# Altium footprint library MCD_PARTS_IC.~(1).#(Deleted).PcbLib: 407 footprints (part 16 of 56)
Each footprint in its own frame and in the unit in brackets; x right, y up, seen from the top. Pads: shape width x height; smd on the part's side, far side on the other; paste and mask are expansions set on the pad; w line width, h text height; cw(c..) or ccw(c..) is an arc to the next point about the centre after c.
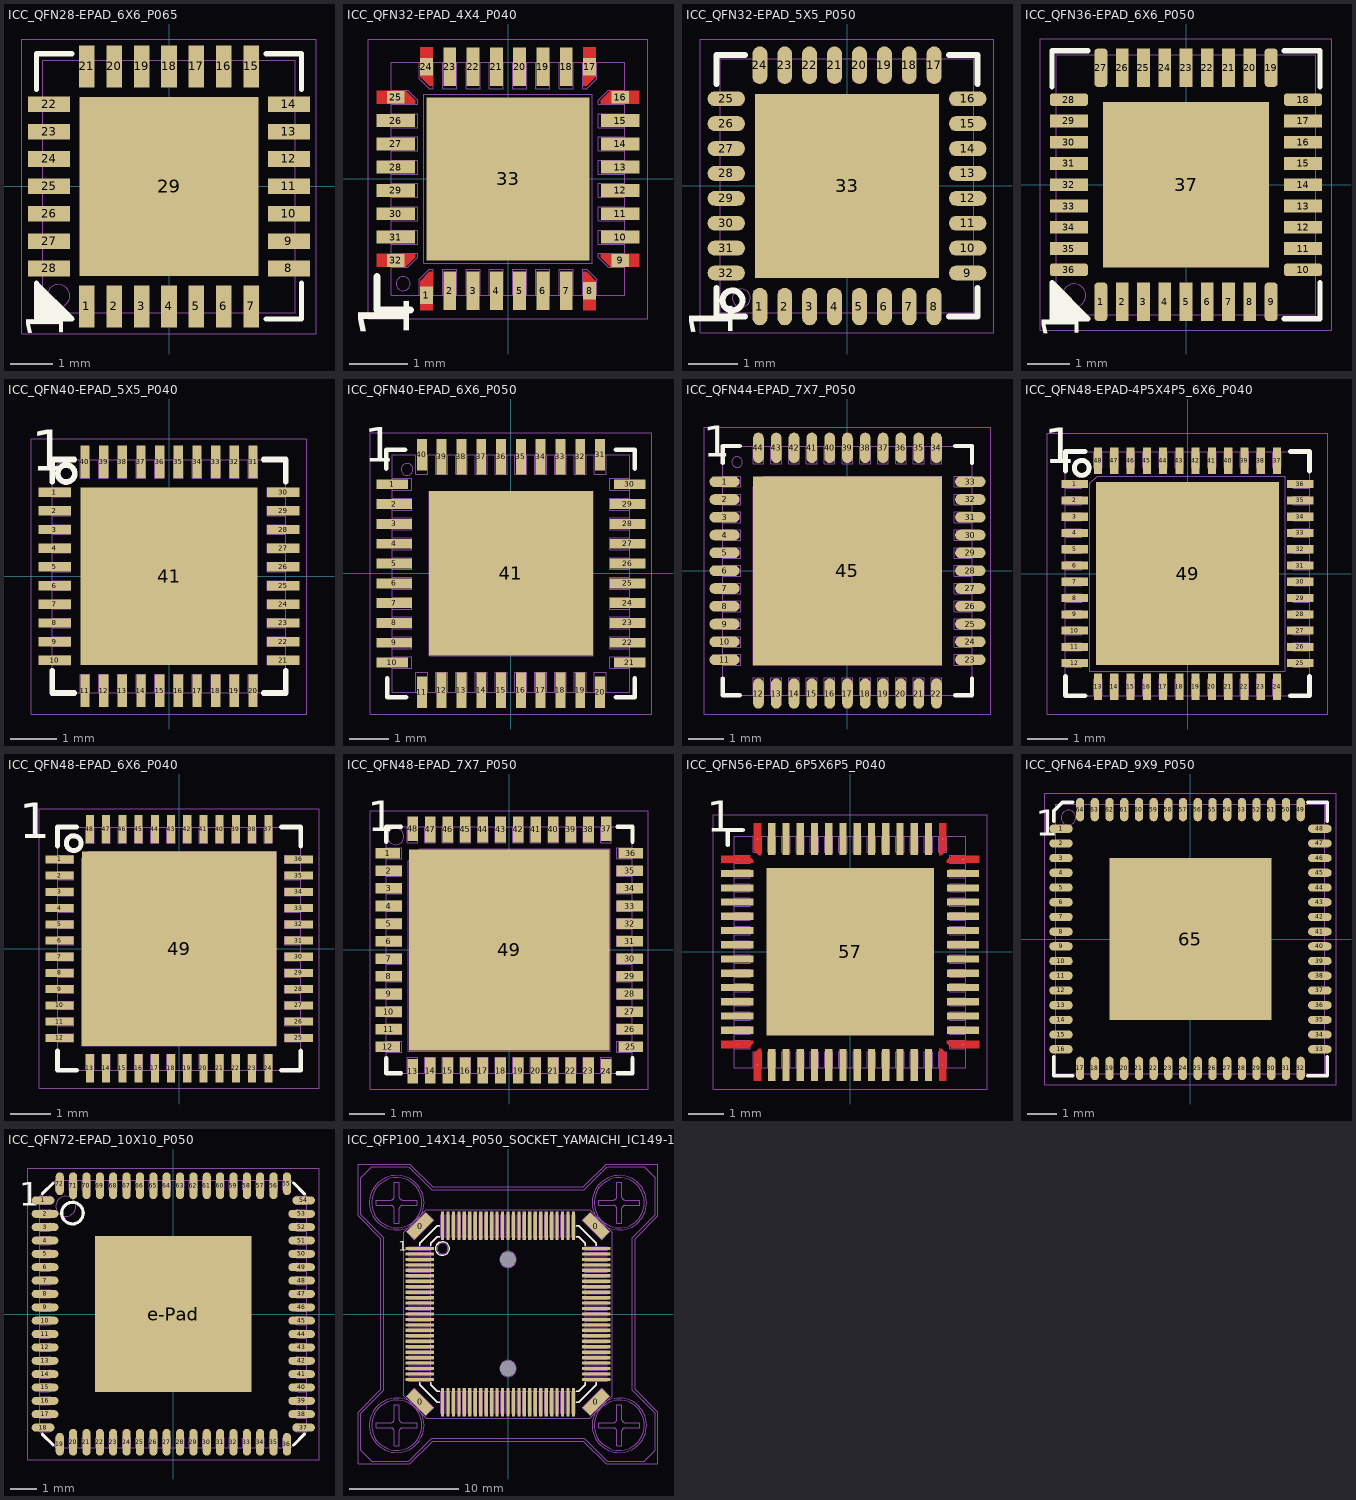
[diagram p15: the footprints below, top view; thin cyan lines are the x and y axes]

## ICC_QFN28-EPAD_6X6_P065 [mm] "MCD-02210"
height 1
pads (29):
  rect 0.37x1 smd mask+0.05: 1(-1.95,-2.85) 2(-1.3,-2.85) 3(-0.65,-2.85) 4(0,-2.85) 5(0.65,-2.85) 6(1.3,-2.85) 7(1.95,-2.85) 15(1.95,2.85) 16(1.3,2.85) 17(0.65,2.85) 18(0,2.85) 19(-0.65,2.85) 20(-1.3,2.85) 21(-1.95,2.85)
  rect 1x0.37 smd mask+0.05: 8(2.85,-1.95) 9(2.85,-1.3) 10(2.85,-0.65) 11(2.85,0) 12(2.85,0.65) 13(2.85,1.3) 14(2.85,1.95) 22(-2.85,1.95) 23(-2.85,1.3) 24(-2.85,0.65) 25(-2.85,0) 26(-2.85,-0.65) 27(-2.85,-1.3) 28(-2.85,-1.95)
  rect 4.25x4.25 smd mask+0.05: 29(0,0)
Top Overlay:
  lines w0.12: -3.15,-2.9 -2.9,-3.15 ; -3.15,-2.75 -2.75,-3.15 ; -3.15,-2.6 -2.6,-3.15 ; -3.15,-2.45 -2.45,-3.15 ; -3.15,2.3 -3.15,3.15 -2.3,3.15 ; -2.75,-2.75 -3.15,-3.15 ; 2.3,-3.15 3.15,-3.15 3.15,-2.3 ; 2.3,3.15 3.15,3.15 3.15,2.3 ; -3.15,-3.15 -2.3,-3.15 -3.15,-2.3 -3.15,-3.15
  text "1" at -2.225,-3.625 h1.5
M14-Top Assembly:
  circle w0.01: c-2.625,-2.6 r0.27
  lines w0.01: -3,-3 3,-3 3,3 -3,3 -3,-3
  text "'.Designator'" at -2,-0.5 h0.75
M16-Top Courtyard:
  lines w0.01: -3.5,-3.5 3.5,-3.5 3.5,3.5 -3.5,3.5 -3.5,-3.5
3D body "User Library-QFN 28-Pin 0_65mm Pitch.STEP": height 1, standoff 0, extent -3.01,-3.01 3.01,3.01
3D body: height 1, standoff 0, extent -3.055,-3.055 3.055,3.055

## ICC_QFN32-EPAD_4X4_P040 [mm]
height 0.9
pads (33):
  rect 0.22x0.3 smd mask+0.05: 1(-1.4,-2) 8(1.4,-1.925) 17(1.4,1.925) 24(-1.4,1.925)
  rect 0.22x0.66 smd mask+0.05: 2(-1,-1.925) 3(-0.6,-1.925) 4(-0.2,-1.925) 5(0.2,-1.925) 6(0.6,-1.925) 7(1,-1.925) 18(1,1.925) 19(0.6,1.925) 20(0.2,1.925) 21(-0.2,1.925) 22(-0.6,1.925) 23(-1,1.925)
  rect 0.3x0.22 smd mask+0.05: 9(1.925,-1.4) 16(1.925,1.4) 25(-1.925,1.4) 32(-1.925,-1.4)
  rect 0.66x0.22 smd mask+0.05: 10(1.925,-1) 11(1.925,-0.6) 12(1.925,-0.2) 13(1.925,0.2) 14(1.925,0.6) 15(1.925,1) 26(-1.925,1) 27(-1.925,0.6) 28(-1.925,0.2) 29(-1.925,-0.2) 30(-1.925,-0.6) 31(-1.925,-1)
  rect 2.8x2.8 smd mask+0.05: 33(0,0)
Top Layer:
  region: 1.29,-2.255 1.29,-1.595 1.35,-1.595 1.51,-1.755 1.51,-2.255
  region: -1.29,-2.255 -1.29,-1.595 -1.35,-1.595 -1.51,-1.755 -1.51,-2.255
  region: -2.255,-1.29 -1.595,-1.29 -1.595,-1.35 -1.755,-1.51 -2.255,-1.51
  region: -2.255,1.29 -1.595,1.29 -1.595,1.35 -1.755,1.51 -2.255,1.51
  region: 2.255,1.29 1.595,1.29 1.595,1.35 1.755,1.51 2.255,1.51
  region: 2.255,-1.29 1.595,-1.29 1.595,-1.35 1.755,-1.51 2.255,-1.51
  region: 1.29,2.255 1.29,1.595 1.35,1.595 1.51,1.755 1.51,2.255
  region: -1.29,2.255 -1.29,1.595 -1.35,1.595 -1.51,1.755 -1.51,2.255
Top Overlay:
  lines w0.12: -2.25,-1.675 -2.25,-2.25 -1.675,-2.25
  text "1" at -1.4,-2.75 h1.5
M14-Top Assembly:
  circle w0.01: c-1.8,-1.8 r0.12
  lines w0.01: -2,-1.52 -1.72,-1.52 -1.55,-1.35 -1.55,-1.28 -2,-1.28 ; -2,-1.12 -1.55,-1.12 -1.55,-0.88 -2,-0.88 ; -2,-0.72 -1.55,-0.72 -1.55,-0.48 -2,-0.48 ; -2,-0.32 -1.55,-0.32 -1.55,-0.08 -2,-0.08 ; -2,0.08 -1.55,0.08 -1.55,0.32 -2,0.32 ; -2,0.48 -1.55,0.48 -1.55,0.72 -2,0.72 ; -2,0.88 -1.55,0.88 -1.55,1.12 -2,1.12 ; -2,1.28 -1.55,1.28 -1.55,1.35 -1.72,1.52 -2,1.52 ; -1.52,-2 -1.52,-1.72 -1.35,-1.55 -1.28,-1.55 -1.28,-2 ; -1.52,2 -1.52,1.72 -1.35,1.55 -1.28,1.55 -1.28,2 ; -1.12,-2 -1.12,-1.55 -0.88,-1.55 -0.88,-2 ; -1.12,2 -1.12,1.55 -0.88,1.55 -0.88,2 ; -0.72,-2 -0.72,-1.55 -0.48,-1.55 -0.48,-2 ; -0.72,2 -0.72,1.55 -0.48,1.55 -0.48,2 ; -0.32,-2 -0.32,-1.55 -0.08,-1.55 -0.08,-2 ; -0.32,2 -0.32,1.55 -0.08,1.55 -0.08,2 ; 0.08,-2 0.08,-1.55 0.32,-1.55 0.32,-2 ; 0.08,2 0.08,1.55 0.32,1.55 0.32,2 ; 0.48,-2 0.48,-1.55 0.72,-1.55 0.72,-2 ; 0.48,2 0.48,1.55 0.72,1.55 0.72,2 ; 0.88,-2 0.88,-1.55 1.12,-1.55 1.12,-2 ; 0.88,2 0.88,1.55 1.12,1.55 1.12,2 ; 1.28,-2 1.28,-1.55 1.35,-1.55 1.52,-1.72 1.52,-2 ; 1.28,2 1.28,1.55 1.35,1.55 1.52,1.72 1.52,2 ; 2,-1.52 1.72,-1.52 1.55,-1.35 1.55,-1.28 2,-1.28 ; 2,-1.12 1.55,-1.12 1.55,-0.88 2,-0.88 ; 2,-0.72 1.55,-0.72 1.55,-0.48 2,-0.48 ; 2,-0.32 1.55,-0.32 1.55,-0.08 2,-0.08 ; 2,0.08 1.55,0.08 1.55,0.32 2,0.32 ; 2,0.48 1.55,0.48 1.55,0.72 2,0.72 ; 2,0.88 1.55,0.88 1.55,1.12 2,1.12 ; 2,1.28 1.55,1.28 1.55,1.35 1.72,1.52 2,1.52 ; -2,-2 -2,2 2,2 2,-2 -2,-2 ; -1.45,-1.45 -1.45,1.45 1.45,1.45 1.45,-1.45 -1.45,-1.45
  text "33" at -0.275,-0.15 h0.5
  text "8" at 1.3,-1.95 h0.5
  text "1" at -1.475,-1.95 h0.5
  text "'.Designator'" at 0,0 h0.75
  text "16" at 1.95,1.2 h0.5
  text "9" at 1.95,-1.475 h0.5
  text "24" at -1.15,1.95 h0.5
  text "17" at 1.625,1.95 h0.5
  text "32" at -1.95,-1.125 h0.5
  text "25" at -1.95,1.625 h0.5
M16-Top Courtyard:
  lines w0.01: -2.4,-2.4 2.4,-2.4 2.4,2.4 -2.4,2.4 -2.4,-2.4
3D body: height 0.9, standoff 0, extent -2.005,-2.005 2.005,2.005
3D body: height 0.91, standoff 0.9, extent -1.92,-1.92 -1.68,-1.68

## ICC_QFN32-EPAD_5X5_P050 [mm]
height 1
pads (33):
  oval 0.3x0.75 smd mask+0.05: 1(-1.75,-2.425) 2(-1.25,-2.425) 3(-0.75,-2.425) 4(-0.25,-2.425) 5(0.25,-2.425) 6(0.75,-2.425) 7(1.25,-2.425) 8(1.75,-2.425) 17(1.75,2.425) 18(1.25,2.425) 19(0.75,2.425) 20(0.25,2.425) 21(-0.25,2.425) 22(-0.75,2.425) 23(-1.25,2.425) 24(-1.75,2.425)
  oval 0.75x0.3 smd mask+0.05: 9(2.425,-1.75) 10(2.425,-1.25) 11(2.425,-0.75) 12(2.425,-0.25) 13(2.425,0.25) 14(2.425,0.75) 15(2.425,1.25) 16(2.425,1.75) 25(-2.425,1.75) 26(-2.425,1.25) 27(-2.425,0.75) 28(-2.425,0.25) 29(-2.425,-0.25) 30(-2.425,-0.75) 31(-2.425,-1.25) 32(-2.425,-1.75)
  rect 3.7x3.7 smd mask+0.05: 33(0,0)
Top Overlay:
  circle w0.12: c-2.3,-2.3 r0.2
  lines w0.12: -2.625,-2.05 -2.625,-2.625 -2.05,-2.625 ; -2.625,2.05 -2.625,2.625 -2.05,2.625 ; 2.05,-2.625 2.625,-2.625 2.625,-2.05 ; 2.05,2.625 2.625,2.625 2.625,2.05
  text "1" at -2,-3.075 h1.5
M14-Top Assembly:
  circle w0.01: c-2.125,-2.25 r0.18
  lines w0.01: -2.55,-1.87 -2.1,-1.87 -2.1,-1.63 -2.55,-1.63 ; -2.55,-1.37 -2.1,-1.37 -2.1,-1.13 -2.55,-1.13 ; -2.55,-0.87 -2.1,-0.87 -2.1,-0.63 -2.55,-0.63 ; -2.55,-0.37 -2.1,-0.37 -2.1,-0.13 -2.55,-0.13 ; -2.55,0.13 -2.1,0.13 -2.1,0.37 -2.55,0.37 ; -2.55,0.63 -2.1,0.63 -2.1,0.87 -2.55,0.87 ; -2.55,1.13 -2.1,1.13 -2.1,1.37 -2.55,1.37 ; -2.55,1.63 -2.1,1.63 -2.1,1.87 -2.55,1.87 ; -1.87,-2.55 -1.87,-2.1 -1.63,-2.1 -1.63,-2.55 ; -1.87,2.55 -1.87,2.1 -1.63,2.1 -1.63,2.55 ; -1.37,-2.55 -1.37,-2.1 -1.13,-2.1 -1.13,-2.55 ; -1.37,2.55 -1.37,2.1 -1.13,2.1 -1.13,2.55 ; -0.87,-2.55 -0.87,-2.1 -0.63,-2.1 -0.63,-2.55 ; -0.87,2.55 -0.87,2.1 -0.63,2.1 -0.63,2.55 ; -0.37,-2.55 -0.37,-2.1 -0.13,-2.1 -0.13,-2.55 ; -0.37,2.55 -0.37,2.1 -0.13,2.1 -0.13,2.55 ; 0.13,-2.55 0.13,-2.1 0.37,-2.1 0.37,-2.55 ; 0.13,2.55 0.13,2.1 0.37,2.1 0.37,2.55 ; 0.63,-2.55 0.63,-2.1 0.87,-2.1 0.87,-2.55 ; 0.63,2.55 0.63,2.1 0.87,2.1 0.87,2.55 ; 1.13,-2.55 1.13,-2.1 1.37,-2.1 1.37,-2.55 ; 1.13,2.55 1.13,2.1 1.37,2.1 1.37,2.55 ; 1.63,-2.55 1.63,-2.1 1.87,-2.1 1.87,-2.55 ; 1.63,2.55 1.63,2.1 1.87,2.1 1.87,2.55 ; 2.55,-1.87 2.1,-1.87 2.1,-1.63 2.55,-1.63 ; 2.55,-1.37 2.1,-1.37 2.1,-1.13 2.55,-1.13 ; 2.55,-0.87 2.1,-0.87 2.1,-0.63 2.55,-0.63 ; 2.55,-0.37 2.1,-0.37 2.1,-0.13 2.55,-0.13 ; 2.55,0.13 2.1,0.13 2.1,0.37 2.55,0.37 ; 2.55,0.63 2.1,0.63 2.1,0.87 2.55,0.87 ; 2.55,1.13 2.1,1.13 2.1,1.37 2.55,1.37 ; 2.55,1.63 2.1,1.63 2.1,1.87 2.55,1.87 ; -2.55,-2.55 -2.55,2.55 2.55,2.55 2.55,-2.55 -2.55,-2.55 ; -1.8,-1.787 -1.8,1.82 1.807,1.82 1.807,-1.787 -1.8,-1.787
  text "33" at -0.275,-0.15 h0.5
  text "32" at -2.45,-1.525 h0.5
  text "25" at -2.45,2 h0.5
  text "24" at -1.975,2.175 h0.5
  text "17" at 1.55,2.15 h0.5
  text "16" at 2.45,1.575 h0.5
  text "9" at 2.45,-1.85 h0.5
  text "8" at 1.65,-2.475 h0.5
  text "1" at -1.8,-2.475 h0.5
  text "'.Designator'" at -2,0.25 h0.75
M16-Top Courtyard:
  lines w0.01: -2.95,-2.95 2.95,-2.95 2.95,2.95 -2.95,2.95 -2.95,-2.95
3D body: height 1, standoff 0, extent -2.55,-2.55 2.55,2.55
3D body "QFN32-EPAD_5X5_P050.STEP": height 0.9, standoff -0.03, extent -2.5,-2.5 2.5,2.5

## ICC_QFN36-EPAD_6X6_P050 [mm]
height 1
pads (37):
  rrect50% 0.3x0.9 smd mask+0.05: 1(-2,-2.75) 9(2,-2.75) 19(2,2.75) 27(-2,2.75)
  rect 0.3x0.9 smd mask+0.05: 2(-1.5,-2.75) 3(-1,-2.75) 4(-0.5,-2.75) 5(0,-2.75) 6(0.5,-2.75) 7(1,-2.75) 8(1.5,-2.75) 20(1.5,2.75) 21(1,2.75) 22(0.5,2.75) 23(0,2.75) 24(-0.5,2.75) 25(-1,2.75) 26(-1.5,2.75)
  rrect50% 0.9x0.3 smd mask+0.05: 10(2.75,-2) 18(2.75,2) 28(-2.75,2) 36(-2.75,-2)
  rect 0.9x0.3 smd mask+0.05: 11(2.75,-1.5) 12(2.75,-1) 13(2.75,-0.5) 14(2.75,0) 15(2.75,0.5) 16(2.75,1) 17(2.75,1.5) 29(-2.75,1.5) 30(-2.75,1) 31(-2.75,0.5) 32(-2.75,0) 33(-2.75,-0.5) 34(-2.75,-1) 35(-2.75,-1.5)
  rect 3.9x3.9 smd mask+0.05: 37(0,0)
Top Overlay:
  lines w0.12: -3.15,-2.9 -2.9,-3.15 ; -3.15,-2.75 -2.75,-3.15 ; -3.15,-2.6 -2.6,-3.15 ; -3.15,-2.45 -2.45,-3.15 ; -3.15,2.3 -3.15,3.15 -2.3,3.15 ; -2.75,-2.75 -3.15,-3.15 ; 2.3,-3.15 3.15,-3.15 3.15,-2.3 ; 2.3,3.15 3.15,3.15 3.15,2.3 ; -3.15,-3.15 -3.15,-2.3 -2.3,-3.15 -3.15,-3.15
  text "1" at -2.225,-3.625 h1.5
M14-Top Assembly:
  circle w0.01: c-2.625,-2.6 r0.27
  lines w0.01: -3.05,-3.05 3.05,-3.05 3.05,3.05 -3.05,3.05 -3.05,-3.05
  text "'.Designator'" at -2,-0.5 h0.75
M16-Top Courtyard:
  lines w0.01: -3.425,-3.425 -3.425,3.425 3.425,3.425 3.425,-3.425 -3.425,-3.425
3D body: height 1, standoff 0, extent -3.055,-3.055 3.055,3.055
3D body "QFN36-EPAD_6X6_P050.STEP": height 0.8, standoff 0, extent -3.06,-3.06 3.06,3.06

## ICC_QFN40-EPAD_5X5_P040 [mm]
height 0.9
pads (41):
  rect 0.7x0.2 smd mask+0.05: 1(-2.45,1.8) 2(-2.45,1.4) 3(-2.45,1) 4(-2.45,0.6) 5(-2.45,0.2) 6(-2.45,-0.2) 7(-2.45,-0.6) 8(-2.45,-1) 9(-2.45,-1.4) 10(-2.45,-1.8) 21(2.45,-1.8) 22(2.45,-1.4) 23(2.45,-1) 24(2.45,-0.6) 25(2.45,-0.2) 26(2.45,0.2) 27(2.45,0.6) 28(2.45,1) 29(2.45,1.4) 30(2.45,1.8)
  rect 0.2x0.7 smd mask+0.05: 11(-1.8,-2.45) 12(-1.4,-2.45) 13(-1,-2.45) 14(-0.6,-2.45) 15(-0.2,-2.45) 16(0.2,-2.45) 17(0.6,-2.45) 18(1,-2.45) 19(1.4,-2.45) 20(1.8,-2.45) 31(1.8,2.45) 32(1.4,2.45) 33(1,2.45) 34(0.6,2.45) 35(0.2,2.45) 36(-0.2,2.45) 37(-0.6,2.45) 38(-1,2.45) 39(-1.4,2.45) 40(-1.8,2.45)
  rect 3.8x3.8 smd mask+0.05: 41(0,0)
Top Overlay:
  circle w0.12: c-2.2,2.2 r0.182
  lines w0.12: -2.5,-2.025 -2.5,-2.5 -2.025,-2.5 ; -2.5,2.025 -2.5,2.5 -2.025,2.5 ; 2.025,-2.5 2.5,-2.5 2.5,-2.025 ; 2.025,2.5 2.5,2.5 2.5,2.025
  text "1" at -2.95,1.975 h1.5
M14-Top Assembly:
  circle w0.01: c-2.225,2.225 r0.23
  lines w0.01: -2.5,-1.9 -2.1,-1.9 -2.1,-1.7 -2.5,-1.7 ; -2.5,-1.5 -2.1,-1.5 -2.1,-1.3 -2.5,-1.3 ; -2.5,-1.1 -2.1,-1.1 -2.1,-0.9 -2.5,-0.9 ; -2.5,-0.7 -2.1,-0.7 -2.1,-0.5 -2.5,-0.5 ; -2.5,-0.3 -2.1,-0.3 -2.1,-0.1 -2.5,-0.1 ; -2.5,0.1 -2.1,0.1 -2.1,0.3 -2.5,0.3 ; -2.5,0.5 -2.1,0.5 -2.1,0.7 -2.5,0.7 ; -2.5,0.9 -2.1,0.9 -2.1,1.1 -2.5,1.1 ; -2.5,1.3 -2.1,1.3 -2.1,1.5 -2.5,1.5 ; -2.5,1.7 -2.1,1.7 -2.1,1.9 -2.5,1.9 ; -1.9,-2.5 -1.9,-2.1 -1.7,-2.1 -1.7,-2.5 ; -1.9,2.5 -1.9,2.1 -1.7,2.1 -1.7,2.5 ; -1.5,-2.5 -1.5,-2.1 -1.3,-2.1 -1.3,-2.5 ; -1.5,2.5 -1.5,2.1 -1.3,2.1 -1.3,2.5 ; -1.1,-2.5 -1.1,-2.1 -0.9,-2.1 -0.9,-2.5 ; -1.1,2.5 -1.1,2.1 -0.9,2.1 -0.9,2.5 ; -0.7,-2.5 -0.7,-2.1 -0.5,-2.1 -0.5,-2.5 ; -0.7,2.5 -0.7,2.1 -0.5,2.1 -0.5,2.5 ; -0.3,-2.5 -0.3,-2.1 -0.1,-2.1 -0.1,-2.5 ; -0.3,2.5 -0.3,2.1 -0.1,2.1 -0.1,2.5 ; 0.1,-2.5 0.1,-2.1 0.3,-2.1 0.3,-2.5 ; 0.1,2.5 0.1,2.1 0.3,2.1 0.3,2.5 ; 0.5,-2.5 0.5,-2.1 0.7,-2.1 0.7,-2.5 ; 0.5,2.5 0.5,2.1 0.7,2.1 0.7,2.5 ; 0.9,-2.5 0.9,-2.1 1.1,-2.1 1.1,-2.5 ; 0.9,2.5 0.9,2.1 1.1,2.1 1.1,2.5 ; 1.3,-2.5 1.3,-2.1 1.5,-2.1 1.5,-2.5 ; 1.3,2.5 1.3,2.1 1.5,2.1 1.5,2.5 ; 1.7,-2.5 1.7,-2.1 1.9,-2.1 1.9,-2.5 ; 1.7,2.5 1.7,2.1 1.9,2.1 1.9,2.5 ; 2.5,-1.9 2.1,-1.9 2.1,-1.7 2.5,-1.7 ; 2.5,-1.5 2.1,-1.5 2.1,-1.3 2.5,-1.3 ; 2.5,-1.1 2.1,-1.1 2.1,-0.9 2.5,-0.9 ; 2.5,-0.7 2.1,-0.7 2.1,-0.5 2.5,-0.5 ; 2.5,-0.3 2.1,-0.3 2.1,-0.1 2.5,-0.1 ; 2.5,0.1 2.1,0.1 2.1,0.3 2.5,0.3 ; 2.5,0.5 2.1,0.5 2.1,0.7 2.5,0.7 ; 2.5,0.9 2.1,0.9 2.1,1.1 2.5,1.1 ; 2.5,1.3 2.1,1.3 2.1,1.5 2.5,1.5 ; 2.5,1.7 2.1,1.7 2.1,1.9 2.5,1.9 ; -2.5,-2.5 2.5,-2.5 2.5,2.5 -2.5,2.5 -2.5,-2.5 ; -1.85,-1.85 -1.85,1.85 1.85,1.85 1.85,-1.85 -1.85,-1.85
  text "'.Designator'" at -2,0 h0.75
  text "40" at -1.95,2.125 h0.5
  text "31" at 1.6,2.125 h0.5
  text "30" at 2,1.65 h0.5
  text "21" at 2.05,-1.95 h0.5
  text "20" at 1.575,-2.45 h0.5
  text "11" at -1.975,-2.45 h0.5
  text "10" at -2.45,-1.95 h0.5
  text "1" at -2.35,1.65 h0.5
  text "41" at -0.225,-0.15 h0.5
M16-Top Courtyard:
  lines w0.01: -2.95,-2.95 -2.95,2.95 -1.95,2.95 2.95,2.95 2.95,-2.95 -2.95,-2.95
3D body: height 0.74, standoff 0.73, extent -2.248,1.551 -1.75,2.05
3D body: height 0.73, standoff 0.73, extent -2.5,-2.5 2.5,2.5
3D body "QFN40-5X5-P040.STEP": height 0.73, standoff -0.02, extent -2.501,-2.501 2.501,2.501
3D body: height 0.9, standoff 0, extent -2.5,-2.5 2.5,2.5
3D body: height 0.91, standoff 0.9, extent -2.248,1.751 -1.75,2.25

## ICC_QFN40-EPAD_6X6_P050 [mm]
height 0.9
pads (41):
  rect 0.8x0.25 smd mask+0.05: 1(-3,2.25) 10(-3,-2.25) 21(3,-2.25) 30(3,2.25)
  rect 0.9x0.25 smd mask+0.05: 2(-2.95,1.75) 3(-2.95,1.25) 4(-2.95,0.75) 5(-2.95,0.25) 6(-2.95,-0.25) 7(-2.95,-0.75) 8(-2.95,-1.25) 9(-2.95,-1.75) 22(2.95,-1.75) 23(2.95,-1.25) 24(2.95,-0.75) 25(2.95,-0.25) 26(2.95,0.25) 27(2.95,0.75) 28(2.95,1.25) 29(2.95,1.75)
  rect 0.25x0.8 smd mask+0.05: 11(-2.25,-3) 20(2.25,-3) 31(2.25,3) 40(-2.25,3)
  rect 0.25x0.9 smd mask+0.05: 12(-1.75,-2.95) 13(-1.25,-2.95) 14(-0.75,-2.95) 15(-0.25,-2.95) 16(0.25,-2.95) 17(0.75,-2.95) 18(1.25,-2.95) 19(1.75,-2.95) 32(1.75,2.95) 33(1.25,2.95) 34(0.75,2.95) 35(0.25,2.95) 36(-0.25,2.95) 37(-0.75,2.95) 38(-1.25,2.95) 39(-1.75,2.95)
  rect 4.15x4.15 smd mask+0.05: 41(0,0)
Top Overlay:
  lines w0.12: -3.15,2.65 -3.15,3.125 -2.675,3.125 ; -3.125,-2.65 -3.125,-3.125 -2.65,-3.125 ; 2.65,-3.125 3.125,-3.125 3.125,-2.65 ; 2.65,3.125 3.125,3.125 3.125,2.65
  text "1" at -3.7,2.525 h1.5
M14-Top Assembly:
  circle w0.01: c-2.625,2.625 r0.15
  lines w0.01: -3,-2.4 -2.5,-2.4 -2.5,-2.1 -3,-2.1 ; -3,-1.9 -2.5,-1.9 -2.5,-1.6 -3,-1.6 ; -3,-1.4 -2.5,-1.4 -2.5,-1.1 -3,-1.1 ; -3,-0.9 -2.5,-0.9 -2.5,-0.6 -3,-0.6 ; -3,-0.4 -2.5,-0.4 -2.5,-0.1 -3,-0.1 ; -3,0.1 -2.5,0.1 -2.5,0.4 -3,0.4 ; -3,0.6 -2.5,0.6 -2.5,0.9 -3,0.9 ; -3,1.1 -2.5,1.1 -2.5,1.4 -3,1.4 ; -3,1.6 -2.5,1.6 -2.5,1.9 -3,1.9 ; -3,2.1 -2.5,2.1 -2.5,2.4 -3,2.4 ; -2.4,-3 -2.4,-2.5 -2.1,-2.5 -2.1,-3 ; -2.4,3 -2.4,2.5 -2.1,2.5 -2.1,3 ; -2.075,2.075 2.075,2.075 2.075,-2.075 -2.068,-2.075 -2.068,2.075 ; -1.9,-3 -1.9,-2.5 -1.6,-2.5 -1.6,-3 ; -1.9,3 -1.9,2.5 -1.6,2.5 -1.6,3 ; -1.4,-3 -1.4,-2.5 -1.1,-2.5 -1.1,-3 ; -1.4,3 -1.4,2.5 -1.1,2.5 -1.1,3 ; -0.9,-3 -0.9,-2.5 -0.6,-2.5 -0.6,-3 ; -0.9,3 -0.9,2.5 -0.6,2.5 -0.6,3 ; -0.4,-3 -0.4,-2.5 -0.1,-2.5 -0.1,-3 ; -0.4,3 -0.4,2.5 -0.1,2.5 -0.1,3 ; 0.1,-3 0.1,-2.5 0.4,-2.5 0.4,-3 ; 0.1,3 0.1,2.5 0.4,2.5 0.4,3 ; 0.6,-3 0.6,-2.5 0.9,-2.5 0.9,-3 ; 0.6,3 0.6,2.5 0.9,2.5 0.9,3 ; 1.1,-3 1.1,-2.5 1.4,-2.5 1.4,-3 ; 1.1,3 1.1,2.5 1.4,2.5 1.4,3 ; 1.6,-3 1.6,-2.5 1.9,-2.5 1.9,-3 ; 1.6,3 1.6,2.5 1.9,2.5 1.9,3 ; 2.1,-3 2.1,-2.5 2.4,-2.5 2.4,-3 ; 2.1,3 2.1,2.5 2.4,2.5 2.4,3 ; 3,-2.4 2.5,-2.4 2.5,-2.1 3,-2.1 ; 3,-1.9 2.5,-1.9 2.5,-1.6 3,-1.6 ; 3,-1.4 2.5,-1.4 2.5,-1.1 3,-1.1 ; 3,-0.9 2.5,-0.9 2.5,-0.6 3,-0.6 ; 3,-0.4 2.5,-0.4 2.5,-0.1 3,-0.1 ; 3,0.1 2.5,0.1 2.5,0.4 3,0.4 ; 3,0.6 2.5,0.6 2.5,0.9 3,0.9 ; 3,1.1 2.5,1.1 2.5,1.4 3,1.4 ; 3,1.6 2.5,1.6 2.5,1.9 3,1.9 ; 3,2.1 2.5,2.1 2.5,2.4 3,2.4 ; -3,-3 3,-3 3,3 -3,3 -3,-3
  text "'.Designator'" at -2,-0.5 h0.75
  text "40" at -2.5,2.6 h0.5
  text "31" at 2.025,2.6 h0.5
  text "30" at 2.525,2.1 h0.5
  text "21" at 2.525,-2.4 h0.5
  text "20" at 2.025,-2.925 h0.5
  text "11" at -2.45,-2.925 h0.5
  text "10" at -2.95,-2.4 h0.5
  text "1" at -2.8,2.1 h0.5
  text "41" at -0.225,-0.15 h0.5
M16-Top Courtyard:
  lines w0.01: -3.55,-3.55 -3.55,3.55 3.55,3.55 3.55,-3.55 -3.55,-3.55
3D body: height 0.91, standoff 0.9, extent -2.875,2.375 -2.375,2.875
3D body: height 0.9, standoff 0, extent -3,-3 3,3

## ICC_QFN44-EPAD_7X7_P050 [mm] "MCD-04124"
height 0.9
pads (45):
  oval 0.85x0.3 smd mask+0.05: 1(-3.45,2.5) 2(-3.45,2) 3(-3.45,1.5) 4(-3.45,1) 5(-3.45,0.5) 6(-3.45,0) 7(-3.45,-0.5) 8(-3.45,-1) 9(-3.45,-1.5) 10(-3.45,-2) 11(-3.45,-2.5) 23(3.45,-2.5) 24(3.45,-2) 25(3.45,-1.5) 26(3.45,-1) 27(3.45,-0.5) 28(3.45,0) 29(3.45,0.5) 30(3.45,1) 31(3.45,1.5) 32(3.45,2) 33(3.45,2.5)
  oval 0.3x0.85 smd mask+0.05: 12(-2.5,-3.45) 13(-2,-3.45) 14(-1.5,-3.45) 15(-1,-3.45) 16(-0.5,-3.45) 17(0,-3.45) 18(0.5,-3.45) 19(1,-3.45) 20(1.5,-3.45) 21(2,-3.45) 22(2.5,-3.45) 34(2.5,3.45) 35(2,3.45) 36(1.5,3.45) 37(1,3.45) 38(0.5,3.45) 39(0,3.45) 40(-0.5,3.45) 41(-1,3.45) 42(-1.5,3.45) 43(-2,3.45) 44(-2.5,3.45)
  rect 5.3x5.3 smd mask+0.05: 45(0,0)
Top Overlay:
  lines w0.12: -3.5,-3.025 -3.5,-3.5 -3.025,-3.5 ; -3.5,3.025 -3.5,3.5 -3.025,3.5 ; 3.025,-3.5 3.5,-3.5 3.5,-3.025 ; 3.025,3.5 3.5,3.5 3.5,3.025
  text "1" at -4.05,2.9 h1.5
M14-Top Assembly:
  circle w0.01: c-3.1,3.05 r0.15
  lines w0.01: -3.5,-2.65 -3,-2.65 -3,-2.35 -3.5,-2.35 ; -3.5,-2.15 -3,-2.15 -3,-1.85 -3.5,-1.85 ; -3.5,-1.65 -3,-1.65 -3,-1.35 -3.5,-1.35 ; -3.5,-1.15 -3,-1.15 -3,-0.85 -3.5,-0.85 ; -3.5,-0.65 -3,-0.65 -3,-0.35 -3.5,-0.35 ; -3.5,-0.15 -3,-0.15 -3,0.15 -3.5,0.15 ; -3.5,0.35 -3,0.35 -3,0.65 -3.5,0.65 ; -3.5,0.85 -3,0.85 -3,1.15 -3.5,1.15 ; -3.5,1.35 -3,1.35 -3,1.65 -3.5,1.65 ; -3.5,1.85 -3,1.85 -3,2.15 -3.5,2.15 ; -3.5,2.35 -3,2.35 -3,2.65 -3.5,2.65 ; -2.65,-3.5 -2.65,-3 -2.35,-3 -2.35,-3.5 ; -2.65,3.5 -2.65,3 -2.35,3 -2.35,3.5 ; -2.15,-3.5 -2.15,-3 -1.85,-3 -1.85,-3.5 ; -2.15,3.5 -2.15,3 -1.85,3 -1.85,3.5 ; -1.65,-3.5 -1.65,-3 -1.35,-3 -1.35,-3.5 ; -1.65,3.5 -1.65,3 -1.35,3 -1.35,3.5 ; -1.15,-3.5 -1.15,-3 -0.85,-3 -0.85,-3.5 ; -1.15,3.5 -1.15,3 -0.85,3 -0.85,3.5 ; -0.65,-3.5 -0.65,-3 -0.35,-3 -0.35,-3.5 ; -0.65,3.5 -0.65,3 -0.35,3 -0.35,3.5 ; -0.15,-3.5 -0.15,-3 0.15,-3 0.15,-3.5 ; -0.15,3.5 -0.15,3 0.15,3 0.15,3.5 ; 0.35,-3.5 0.35,-3 0.65,-3 0.65,-3.5 ; 0.35,3.5 0.35,3 0.65,3 0.65,3.5 ; 0.85,-3.5 0.85,-3 1.15,-3 1.15,-3.5 ; 0.85,3.5 0.85,3 1.15,3 1.15,3.5 ; 1.35,-3.5 1.35,-3 1.65,-3 1.65,-3.5 ; 1.35,3.5 1.35,3 1.65,3 1.65,3.5 ; 1.85,-3.5 1.85,-3 2.15,-3 2.15,-3.5 ; 1.85,3.5 1.85,3 2.15,3 2.15,3.5 ; 2.35,-3.5 2.35,-3 2.65,-3 2.65,-3.5 ; 2.35,3.5 2.35,3 2.65,3 2.65,3.5 ; 3.5,-2.65 3,-2.65 3,-2.35 3.5,-2.35 ; 3.5,-2.15 3,-2.15 3,-1.85 3.5,-1.85 ; 3.5,-1.65 3,-1.65 3,-1.35 3.5,-1.35 ; 3.5,-1.15 3,-1.15 3,-0.85 3.5,-0.85 ; 3.5,-0.65 3,-0.65 3,-0.35 3.5,-0.35 ; 3.5,-0.15 3,-0.15 3,0.15 3.5,0.15 ; 3.5,0.35 3,0.35 3,0.65 3.5,0.65 ; 3.5,0.85 3,0.85 3,1.15 3.5,1.15 ; 3.5,1.35 3,1.35 3,1.65 3.5,1.65 ; 3.5,1.85 3,1.85 3,2.15 3.5,2.15 ; 3.5,2.35 3,2.35 3,2.65 3.5,2.65 ; -3.5,-3.5 -3.5,3.5 3.5,3.5 3.5,-3.5 -3.5,-3.5 ; -2.65,-2.65 2.65,-2.65 2.65,2.65 -2.35,2.65 -2.65,2.35 -2.65,-2.65
  text "'.Designator'" at -2,-0.5 h0.75
  text "45" at -0.225,-0.15 h0.5
  text "44" at -2.75,3.1 h0.5
  text "34" at 2.275,3.1 h0.5
  text "11" at -3.475,-2.65 h0.5
  text "1" at -3.325,2.35 h0.5
  text "22" at 2.3,-3.4 h0.5
  text "12" at -2.725,-3.4 h0.5
  text "33" at 2.975,2.362 h0.5
  text "23" at 2.975,-2.662 h0.5
M16-Top Courtyard:
  lines w0.01: -4.025,-4.025 -4.025,4.025 4.025,4.025 4.025,-4.025 -4.025,-4.025
3D body: height 0.91, standoff 0.9, extent -3.35,2.825 -2.85,3.325
3D body: height 0.9, standoff 0, extent -3.5,-3.5 3.5,3.5

## ICC_QFN48-EPAD-4P5X4P5_6X6_P040 [mm]
height 0.9
pads (49):
  rect 0.65x0.2 smd mask+0.05: 1(-2.775,2.2) 2(-2.775,1.8) 3(-2.775,1.4) 4(-2.775,1) 5(-2.775,0.6) 6(-2.775,0.2) 7(-2.775,-0.2) 8(-2.775,-0.6) 9(-2.775,-1) 10(-2.775,-1.4) 11(-2.775,-1.8) 12(-2.775,-2.2) 25(2.775,-2.2) 26(2.775,-1.8) 27(2.775,-1.4) 28(2.775,-1) 29(2.775,-0.6) 30(2.775,-0.2) 31(2.775,0.2) 32(2.775,0.6) 33(2.775,1) 34(2.775,1.4) 35(2.775,1.8) 36(2.775,2.2)
  rect 0.2x0.65 smd mask+0.05: 13(-2.2,-2.775) 14(-1.8,-2.775) 15(-1.4,-2.775) 16(-1,-2.775) 17(-0.6,-2.775) 18(-0.2,-2.775) 19(0.2,-2.775) 20(0.6,-2.775) 21(1,-2.775) 22(1.4,-2.775) 23(1.8,-2.775) 24(2.2,-2.775) 37(2.2,2.775) 38(1.8,2.775) 39(1.4,2.775) 40(1,2.775) 41(0.6,2.775) 42(0.2,2.775) 43(-0.2,2.775) 44(-0.6,2.775) 45(-1,2.775) 46(-1.4,2.775) 47(-1.8,2.775) 48(-2.2,2.775)
  rect 4.5x4.5 smd mask+0.05: 49(0,0)
Top Overlay:
  circle w0.12: c-2.6,2.6 r0.182
  lines w0.12: -3,-2.525 -3,-3 -2.525,-3 ; -3,2.525 -3,3 -2.525,3 ; 2.525,-3 3,-3 3,-2.525 ; 2.525,3 3,3 3,2.525
  text "1" at -3.525,2.425 h1.5
M14-Top Assembly:
  drawing of 154 lines, arcs and shapes, not listed
  text "'.Designator'" at -2,-0.5 h0.75
  text "1" at -2.85,2.05 h0.5
  text "12" at -2.95,-2.35 h0.5
  text "13" at -2.45,-2.95 h0.5
  text "24" at 1.975,-2.925 h0.5
  text "25" at 2.575,-2.375 h0.5
  text "36" at 2.525,2.05 h0.5
  text "37" at 2,2.625 h0.5
  text "48" at -2.45,2.625 h0.5
M16-Top Courtyard:
  lines w0.01: -3.45,-3.45 -3.45,3.45 -1.45,3.45 3.45,3.45 3.45,-3.45 -3.45,-3.45
3D body: height 0.61, standoff 0.6, extent -2.848,2.351 -2.35,2.85
3D body: height 0.91, standoff 0.9, extent -2.85,2.35 -2.35,2.85
3D body: height 0.9, standoff 0, extent -3,-3 3,3
3D body: height 0.9, standoff 0, extent -3,-3 3,3

## ICC_QFN48-EPAD_6X6_P040 [mm] "MCD-02431"
height 0.6
pads (49):
  rect 0.7x0.2 smd mask+0.05: 1(-2.95,2.2) 2(-2.95,1.8) 3(-2.95,1.4) 4(-2.95,1) 5(-2.95,0.6) 6(-2.95,0.2) 7(-2.95,-0.2) 8(-2.95,-0.6) 9(-2.95,-1) 10(-2.95,-1.4) 11(-2.95,-1.8) 12(-2.95,-2.2) 25(2.95,-2.2) 26(2.95,-1.8) 27(2.95,-1.4) 28(2.95,-1) 29(2.95,-0.6) 30(2.95,-0.2) 31(2.95,0.2) 32(2.95,0.6) 33(2.95,1) 34(2.95,1.4) 35(2.95,1.8) 36(2.95,2.2)
  rect 0.2x0.7 smd mask+0.05: 13(-2.2,-2.95) 14(-1.8,-2.95) 15(-1.4,-2.95) 16(-1,-2.95) 17(-0.6,-2.95) 18(-0.2,-2.95) 19(0.2,-2.95) 20(0.6,-2.95) 21(1,-2.95) 22(1.4,-2.95) 23(1.8,-2.95) 24(2.2,-2.95) 37(2.2,2.95) 38(1.8,2.95) 39(1.4,2.95) 40(1,2.95) 41(0.6,2.95) 42(0.2,2.95) 43(-0.2,2.95) 44(-0.6,2.95) 45(-1,2.95) 46(-1.4,2.95) 47(-1.8,2.95) 48(-2.2,2.95)
  rect 4.8x4.8 smd mask+0.05: 49(0,0)
Top Overlay:
  circle w0.12: c-2.6,2.6 r0.182
  lines w0.12: -3,-2.525 -3,-3 -2.525,-3 ; -3,2.525 -3,3 -2.525,3 ; 2.525,-3 3,-3 3,-2.525 ; 2.525,3 3,3 3,2.525
  text "1" at -3.95,2.425 h1.5
M14-Top Assembly:
  drawing of 154 lines, arcs and shapes, not listed
  text "'.Designator'" at -2,-0.5 h0.75
  text "1" at -2.85,2.05 h0.5
  text "12" at -2.95,-2.35 h0.5
  text "13" at -2.45,-2.95 h0.5
  text "24" at 1.975,-2.925 h0.5
  text "25" at 2.575,-2.375 h0.5
  text "36" at 2.525,2.05 h0.5
  text "37" at 2,2.625 h0.5
  text "48" at -2.45,2.625 h0.5
M16-Top Courtyard:
  lines w0.01: -3.45,-3.45 -3.45,3.45 -1.45,3.45 3.45,3.45 3.45,-3.45 -3.45,-3.45
3D body: height 0.6, standoff 0, extent -3,-3 3,3
3D body: height 0.61, standoff 0.6, extent -2.848,2.351 -2.35,2.85
3D body: height 0.6, standoff 0, extent -3,-3 3,3
3D body: height 0.61, standoff 0.6, extent -2.848,2.351 -2.35,2.85

## ICC_QFN48-EPAD_7X7_P050 [mm]
height 0.9
pads (49):
  rect 0.7x0.3 smd mask+0.05: 1(-3.45,2.75) 12(-3.45,-2.75) 25(3.45,-2.75) 36(3.45,2.75)
  rect 0.75x0.3 smd mask+0.05: 2(-3.425,2.25) 3(-3.425,1.75) 4(-3.425,1.25) 5(-3.425,0.75) 6(-3.425,0.25) 7(-3.425,-0.25) 8(-3.425,-0.75) 9(-3.425,-1.25) 10(-3.425,-1.75) 11(-3.425,-2.25) 26(3.425,-2.25) 27(3.425,-1.75) 28(3.425,-1.25) 29(3.425,-0.75) 30(3.425,-0.25) 31(3.425,0.25) 32(3.425,0.75) 33(3.425,1.25) 34(3.425,1.75) 35(3.425,2.25)
  rect 0.3x0.7 smd mask+0.05: 13(-2.75,-3.45) 24(2.75,-3.45) 37(2.75,3.45) 48(-2.75,3.45)
  rect 0.3x0.75 smd mask+0.05: 14(-2.25,-3.425) 15(-1.75,-3.425) 16(-1.25,-3.425) 17(-0.75,-3.425) 18(-0.25,-3.425) 19(0.25,-3.425) 20(0.75,-3.425) 21(1.25,-3.425) 22(1.75,-3.425) 23(2.25,-3.425) 38(2.25,3.425) 39(1.75,3.425) 40(1.25,3.425) 41(0.75,3.425) 42(0.25,3.425) 43(-0.25,3.425) 44(-0.75,3.425) 45(-1.25,3.425) 46(-1.75,3.425) 47(-2.25,3.425)
  rect 5.7x5.7 smd mask+0.05: 49(0,0)
Top Overlay:
  lines w0.12: -3.5,-3.075 -3.5,-3.5 -3.075,-3.5 ; -3.5,3.075 -3.5,3.5 -3.075,3.5 ; 3.075,-3.5 3.5,-3.5 3.5,-3.075 ; 3.075,3.5 3.5,3.5 3.5,3.075
  text "1" at -4.025,3.075 h1.5
M14-Top Assembly:
  drawing of 154 lines, arcs and shapes, not listed
  text "'.Designator'" at -2,-0.5 h0.75
  text "1" at -3.35,2.6 h0.5
  text "12" at -3.45,-2.9 h0.5
  text "13" at -3,-3.425 h0.5
  text "24" at 2.525,-3.425 h0.5
  text "25" at 3.025,-2.925 h0.5
  text "36" at 3.05,2.6 h0.5
  text "37" at 2.525,3.125 h0.5
  text "48" at -3,3.1 h0.5
M16-Top Courtyard:
  lines w0.01: -3.95,-3.95 2.6,-3.95 3.95,-3.95 3.95,3.95 -3.95,3.95 -3.95,-3.95
3D body: height 0.9, standoff 0, extent -3.5,-3.5 3.5,3.5
3D body: height 0.91, standoff 0.9, extent -3.473,2.976 -2.975,3.475

## ICC_QFN56-EPAD_6P5X6P5_P040 [mm] "MCD-03000"
height 0.9
pads (57):
  round 0.025 smd mask+0.05: 1(-3.17,2.6) 14(-3.17,-2.6) 15(-2.6,-3.17) 28(2.6,-3.17) 29(3.17,-2.6) 42(3.17,2.6) 43(2.6,3.17) 56(-2.6,3.17)
  rect 0.9x0.2 smd mask+0.05: 2(-3.17,2.2) 3(-3.17,1.8) 4(-3.17,1.4) 5(-3.17,1) 6(-3.17,0.6) 7(-3.17,0.2) 8(-3.17,-0.2) 9(-3.17,-0.6) 10(-3.17,-1) 11(-3.17,-1.4) 12(-3.17,-1.8) 13(-3.17,-2.2) 30(3.17,-2.2) 31(3.17,-1.8) 32(3.17,-1.4) 33(3.17,-1) 34(3.17,-0.6) 35(3.17,-0.2) 36(3.17,0.2) 37(3.17,0.6) 38(3.17,1) 39(3.17,1.4) 40(3.17,1.8) 41(3.17,2.2)
  rect 0.2x0.9 smd mask+0.05: 16(-2.2,-3.17) 17(-1.8,-3.17) 18(-1.4,-3.17) 19(-1,-3.17) 20(-0.6,-3.17) 21(-0.2,-3.17) 22(0.2,-3.17) 23(0.6,-3.17) 24(1,-3.17) 25(1.4,-3.17) 26(1.8,-3.17) 27(2.2,-3.17) 44(2.2,3.17) 45(1.8,3.17) 46(1.4,3.17) 47(1,3.17) 48(0.6,3.17) 49(0.2,3.17) 50(-0.2,3.17) 51(-0.6,3.17) 52(-1,3.17) 53(-1.4,3.17) 54(-1.8,3.17) 55(-2.2,3.17)
  rect 4.7x4.7 smd mask+0.05: 57(0,0)
Top Layer:
  region: -3.62,2.5 -3.62,2.7 -2.85,2.7 -2.72,2.57 -2.72,2.5
  region: -2.57,2.72 -2.7,2.85 -2.7,3.62 -2.5,3.62 -2.5,2.72
  region: 2.5,3.62 2.7,3.62 2.7,2.85 2.57,2.72 2.5,2.72
  region: 2.72,2.57 2.85,2.7 3.62,2.7 3.62,2.5 2.72,2.5
  region: 3.62,-2.5 3.62,-2.7 2.85,-2.7 2.72,-2.57 2.72,-2.5
  region: 2.57,-2.72 2.7,-2.85 2.7,-3.62 2.5,-3.62 2.5,-2.72
  region: -2.5,-3.62 -2.7,-3.62 -2.7,-2.85 -2.57,-2.72 -2.5,-2.72
  region: -2.72,-2.57 -2.85,-2.7 -3.62,-2.7 -3.62,-2.5 -2.72,-2.5
Top Overlay:
  lines w0.12: -3.438,3 -3.438,3.425 -3.013,3.425
  text "1" at -4.025,3.075 h1.5
M14-Top Assembly:
  drawing of 177 lines, arcs and shapes, not listed
  text "'.Designator'" at -2,-0.5 h0.75
  text "1" at -3.1,2.45 h0.5
  text "14" at -3.175,-2.75 h0.5
  text "15" at -2.85,-3.175 h0.5
  text "28" at 2.35,-3.2 h0.5
  text "29" at 2.725,-2.75 h0.5
  text "42" at 2.75,2.45 h0.5
  text "43" at 2.35,2.875 h0.5
  text "56" at -2.875,2.875 h0.5
M16-Top Courtyard:
  lines w0.01: -3.85,-3.85 3.85,-3.85 3.85,3.85 -3.85,3.85 -3.85,-3.85
3D body: height 0.9, standoff 0, extent -3.25,-3.25 3.25,3.25
3D body: height 0.91, standoff 0.9, extent -3.124,2.376 -2.626,2.875

## ICC_QFN64-EPAD_9X9_P050 [mm]
height 1
pads (65):
  oval 0.8x0.28 smd mask+0.05: 1(-4.4,3.75) 2(-4.4,3.25) 3(-4.4,2.75) 4(-4.4,2.25) 5(-4.4,1.75) 6(-4.4,1.25) 7(-4.4,0.75) 8(-4.4,0.25) 9(-4.4,-0.25) 10(-4.4,-0.75) 11(-4.4,-1.25) 12(-4.4,-1.75) 13(-4.4,-2.25) 14(-4.4,-2.75) 15(-4.4,-3.25) 16(-4.4,-3.75) 33(4.4,-3.75) 34(4.4,-3.25) 35(4.4,-2.75) 36(4.4,-2.25) 37(4.4,-1.75) 38(4.4,-1.25) 39(4.4,-0.75) 40(4.4,-0.25) 41(4.4,0.25) 42(4.4,0.75) 43(4.4,1.25) 44(4.4,1.75) 45(4.4,2.25) 46(4.4,2.75) 47(4.4,3.25) 48(4.4,3.75)
  oval 0.28x0.8 smd mask+0.05: 17(-3.75,-4.4) 18(-3.25,-4.4) 19(-2.75,-4.4) 20(-2.25,-4.4) 21(-1.75,-4.4) 22(-1.25,-4.4) 23(-0.75,-4.4) 24(-0.25,-4.4) 25(0.25,-4.4) 26(0.75,-4.4) 27(1.25,-4.4) 28(1.75,-4.4) 29(2.25,-4.4) 30(2.75,-4.4) 31(3.25,-4.4) 32(3.75,-4.4) 49(3.75,4.4) 50(3.25,4.4) 51(2.75,4.4) 52(2.25,4.4) 53(1.75,4.4) 54(1.25,4.4) 55(0.75,4.4) 56(0.25,4.4) 57(-0.25,4.4) 58(-0.75,4.4) 59(-1.25,4.4) 60(-1.75,4.4) 61(-2.25,4.4) 62(-2.75,4.4) 63(-3.25,4.4) 64(-3.75,4.4)
  rect 5.5x5.5 smd mask+0.05: 65(0,0)
Top Overlay:
  lines w0.127: -4.65,-4 -4.65,-4.65 -4,-4.65 ; -4.65,4 -4.65,4.35 -4.35,4.65 -4,4.65 ; 4,-4.65 4.65,-4.65 4.65,-4 ; 4,4.65 4.65,4.65 4.65,4
  text "1" at -5.25,3.225 h1.5
M14-Top Assembly:
  circle w0.01: c-4.15,4.125 r0.25
  lines w0.01: -4.575,-4.575 -4.575,4.575 4.575,4.575 4.575,-4.575 -4.575,-4.575
  text "'.Designator'" at -2,-0.5 h0.75
M16-Top Courtyard:
  lines w0.01: -4.95,-4.95 -4.95,4.95 4.95,4.95 4.95,-4.95 -4.95,-4.95
3D body: height 1, standoff 0, extent -4.58,-4.58 4.58,4.58
3D body: height 0.9, standoff 0, extent -4.51,-4.51 4.51,4.51

## ICC_QFN72-EPAD_10X10_P050 [mm]
height 0.9
pads (73):
  oval 0.85x0.3 smd mask+0.05: 1(-4.875,4.25) 18(-4.875,-4.25) 37(4.875,-4.25) 54(4.875,4.25)
  oval 1x0.3 smd mask+0.05: 2(-4.8,3.75) 3(-4.8,3.25) 4(-4.8,2.75) 5(-4.8,2.25) 6(-4.8,1.75) 7(-4.8,1.25) 8(-4.8,0.75) 9(-4.8,0.25) 10(-4.8,-0.25) 11(-4.8,-0.75) 12(-4.8,-1.25) 13(-4.8,-1.75) 14(-4.8,-2.25) 15(-4.8,-2.75) 16(-4.8,-3.25) 17(-4.8,-3.75) 38(4.8,-3.75) 39(4.8,-3.25) 40(4.8,-2.75) 41(4.8,-2.25) 42(4.8,-1.75) 43(4.8,-1.25) 44(4.8,-0.75) 45(4.8,-0.25) 46(4.8,0.25) 47(4.8,0.75) 48(4.8,1.25) 49(4.8,1.75) 50(4.8,2.25) 51(4.8,2.75) 52(4.8,3.25) 53(4.8,3.75)
  oval 0.3x0.85 smd mask+0.05: 19(-4.25,-4.875) 36(4.25,-4.875) 55(4.25,4.875) 72(-4.25,4.875)
  oval 0.3x1 smd mask+0.05: 20(-3.75,-4.8) 21(-3.25,-4.8) 22(-2.75,-4.8) 23(-2.25,-4.8) 24(-1.75,-4.8) 25(-1.25,-4.8) 26(-0.75,-4.8) 27(-0.25,-4.8) 28(0.25,-4.8) 29(0.75,-4.8) 30(1.25,-4.8) 31(1.75,-4.8) 32(2.25,-4.8) 33(2.75,-4.8) 34(3.25,-4.8) 35(3.75,-4.8) 56(3.75,4.8) 57(3.25,4.8) 58(2.75,4.8) 59(2.25,4.8) 60(1.75,4.8) 61(1.25,4.8) 62(0.75,4.8) 63(0.25,4.8) 64(-0.25,4.8) 65(-0.75,4.8) 66(-1.25,4.8) 67(-1.75,4.8) 68(-2.25,4.8) 69(-2.75,4.8) 70(-3.25,4.8) 71(-3.75,4.8)
  rect 5.85x5.85 smd mask+0.05: e-Pad(0,0)
Top Overlay:
  circle w0.12: c-3.775,3.775 r0.404
  lines w0.12: -4.9,-4.5 -4.5,-4.9 ; -4.9,4.5 -4.5,4.9 ; 4.5,-4.9 4.9,-4.5 ; 4.5,4.9 4.9,4.5
  text "1" at -5.775,3.75 h1.5
M14-Top Assembly:
  drawing of 229 lines, arcs and shapes, not listed
  text "1" at -5.475,3.775 h1.5
  text "'.Designator'" at -2,-0.5 h0.75
M16-Top Courtyard:
  lines w0.01: -5.45,-5.45 -5.45,5.45 5.45,5.45 5.45,-5.45 -5.45,-5.45
3D body: height 0.91, standoff 0.9, extent -4.447,3.651 -3.65,4.449
3D body: height 0.9, standoff 0, extent -5,-5 5,5

## ICC_QFP100_14X14_P050_SOCKET_YAMAICHI_IC149-100-025-B5 [mm] "MCD-01899"
height 13.2
pads (106):
  rect 1x2.5 smd rot 45 mask+0.05: 0(-8.061,-8.061) 0(8.061,8.061)
  rect 1x2.5 smd rot 135 mask+0.05: 0(-8.061,8.061) 0(8.061,-8.061)
  round 0 hole 1.5 unplated mask+0.05: 0(0,-5) 0(0,5)
  rect 2.6x0.3 smd mask+0.05: 1(-8.1,6) 2(-8.1,5.5) 3(-8.1,5) 4(-8.1,4.5) 5(-8.1,4) 6(-8.1,3.5) 7(-8.1,3) 8(-8.1,2.5) 9(-8.1,2) 10(-8.1,1.5) 11(-8.1,1) 12(-8.1,0.5) 13(-8.1,0) 14(-8.1,-0.5) 15(-8.1,-1) 16(-8.1,-1.5) 17(-8.1,-2) 18(-8.1,-2.5) 19(-8.1,-3) 20(-8.1,-3.5) 21(-8.1,-4) 22(-8.1,-4.5) 23(-8.1,-5) 24(-8.1,-5.5) 25(-8.1,-6) 51(8.1,-6) 52(8.1,-5.5) 53(8.1,-5) 54(8.1,-4.5) 55(8.1,-4) 56(8.1,-3.5) 57(8.1,-3) 58(8.1,-2.5) 59(8.1,-2) 60(8.1,-1.5) 61(8.1,-1) 62(8.1,-0.5) 63(8.1,0) 64(8.1,0.5) 65(8.1,1) 66(8.1,1.5) 67(8.1,2) 68(8.1,2.5) 69(8.1,3) 70(8.1,3.5) 71(8.1,4) 72(8.1,4.5) 73(8.1,5) 74(8.1,5.5) 75(8.1,6)
  rect 0.3x2.6 smd mask+0.05: 26(-6,-8.1) 27(-5.5,-8.1) 28(-5,-8.1) 29(-4.5,-8.1) 30(-4,-8.1) 31(-3.5,-8.1) 32(-3,-8.1) 33(-2.5,-8.1) 34(-2,-8.1) 35(-1.5,-8.1) 36(-1,-8.1) 37(-0.5,-8.1) 38(0,-8.1) 39(0.5,-8.1) 40(1,-8.1) 41(1.5,-8.1) 42(2,-8.1) 43(2.5,-8.1) 44(3,-8.1) 45(3.5,-8.1) 46(4,-8.1) 47(4.5,-8.1) 48(5,-8.1) 49(5.5,-8.1) 50(6,-8.1) 76(6,8.1) 77(5.5,8.1) 78(5,8.1) 79(4.5,8.1) 80(4,8.1) 81(3.5,8.1) 82(3,8.1) 83(2.5,8.1) 84(2,8.1) 85(1.5,8.1) 86(1,8.1) 87(0.5,8.1) 88(0,8.1) 89(-0.5,8.1) 90(-1,8.1) 91(-1.5,8.1) 92(-2,8.1) 93(-2.5,8.1) 94(-3,8.1) 95(-3.5,8.1) 96(-4,8.1) 97(-4.5,8.1) 98(-5,8.1) 99(-5.5,8.1) 100(-6,8.1)
Top Overlay:
  circle w0.12: c-6,6 r0.625
  lines w0.12: -8.1,-6.275 -8.1,-6.475 -6.475,-8.1 -6.275,-8.1 ; -8.1,6.275 -8.1,6.475 -6.475,8.1 -6.275,8.1 ; -7.1,-6.275 -7.1,-6.5 -6.5,-7.1 -6.275,-7.1 ; -7.1,6.275 -7.1,6.5 -6.5,7.1 -6.275,7.1 ; 6.275,-8.1 6.475,-8.1 8.1,-6.475 8.1,-6.275 ; 6.275,-7.1 6.5,-7.1 7.1,-6.5 7.1,-6.275 ; 6.275,7.1 6.5,7.1 7.1,6.5 7.1,6.275 ; 6.275,8.1 6.475,8.1 8.1,6.475 8.1,6.275
  text "1" at -10,5.5 h1.5
M7-Top Info:
  lines w0.01: -13.75,-13.75 -13.75,-9.1 -13.75,-9 -11.65,-6.9 -11.65,0 -11.65,6.9 -13.75,9 -13.75,9.1 -13.75,13.75 -9.1,13.75 -9,13.75 -6.9,11.65 0,11.65 6.9,11.65 9,13.75 9.1,13.75 13.75,13.75 13.75,9.1 13.75,9 11.65,6.9 11.65,0 11.65,-6.9 13.75,-9 13.75,-9.1 13.75,-13.75 9.1,-13.75 9,-13.75 6.9,-11.65 0,-11.65 -6.9,-11.65 -9,-13.75 -9.1,-13.75 -13.75,-13.75 ; -9.575,-7.475 -9.575,-6.2 -9.575,6.225 -9.575,7.475 -7.475,9.575 -6.2,9.575 6.225,9.575 7.475,9.575 9.575,7.475 9.575,6.2 9.575,-6.225 9.575,-7.475 7.475,-9.575 -6.225,-9.575 -7.475,-9.575 -9.575,-7.475
  text "AREA AUTHORIZED FOR COMPONENTS LOWER THAN 3.5MM" at -13.2,10.275 h0.7
  text "AREA AUTHORIZED FOR COMPONENTS LOWER THAN 3.5MM" at -10.275,-13.2 h0.7
  text "AREA AUTHORIZED FOR COMPONENTS LOWER THAN 3.5MM" at 10.275,13.2 h0.7
  text "AREA AUTHORIZED FOR COMPONENTS LOWER THAN 3.5MM" at 13.2,-10.275 h0.7
M14-Top Assembly:
  drawing of 871 lines, arcs and shapes, not listed
  text "100" at -5.325,8.075 h1
  text "76" at 6.45,8.075 h1
  text "75" at 8.075,5.525 h1
  text "51" at 8.075,-6.4 h1
  text "50" at 5.55,-8.075 h1
  text "26" at -6.45,-8.075 h1
  text "1" at -8.075,6.125 h1
  text "'.Designator'" at -2,-0.5 h0.75
  text "25" at -8.075,-5.55 h1
M16-Top Courtyard:
  lines w0.01: -13.75,-13.75 -9.1,-13.75 -9,-13.75 -6.9,-11.65 0,-11.65 6.9,-11.65 9,-13.75 9.1,-13.75 13.75,-13.75 13.75,-9.1 13.75,-9 11.65,-6.9 11.65,0 11.65,6.9 13.75,9 13.75,9.1 13.75,13.75 9.1,13.75 9,13.75 6.9,11.65 0,11.65 -6.9,11.65 -9,13.75 -9.1,13.75 -13.75,13.75 -13.75,9.1 -13.75,9 -11.65,6.9 -11.65,0 -11.65,-6.9 -13.75,-9 -13.75,-9.1 -13.75,-13.75 ; -9.575,-7.475 -7.475,-9.575 -6.225,-9.575 7.475,-9.575 9.575,-7.475 9.575,-6.225 9.575,6.2 9.575,7.475 7.475,9.575 6.225,9.575 -6.2,9.575 -7.475,9.575 -9.575,7.475 -9.575,6.225 -9.575,-6.2 -9.575,-7.475
  text "AREA AUTHORIZED FOR COMPONENTS LOWER THAN 3.5MM" at 13.2,-10.275 h0.7
  text "AREA AUTHORIZED FOR COMPONENTS LOWER THAN 3.5MM" at 10.275,13.2 h0.7
  text "AREA AUTHORIZED FOR COMPONENTS LOWER THAN 3.5MM" at -10.275,-13.2 h0.7
  text "AREA AUTHORIZED FOR COMPONENTS LOWER THAN 3.5MM" at -13.2,10.275 h0.7
3D body: height 11, standoff 3.5, extent 0,-13.5 13.5,13.5
3D body: height 11, standoff 3.5, extent -13.5,-13.5 0,13.5
3D body: height 0, standoff -1.6, extent -0.744,4.252 0.75,5.749
3D body: height 0, standoff -1.6, extent -0.744,-5.748 0.75,-4.251
3D body: height 0.2, standoff 0, extent -9.1,3.85 -8.1,4.15
3D body: height 0.2, standoff 0, extent -9.1,4.35 -8.1,4.65
3D body: height 0.2, standoff 0, extent -9.1,4.85 -8.1,5.15
3D body: height 0.2, standoff 0, extent -9.1,5.35 -8.1,5.65
3D body: height 0.2, standoff 0, extent -9.1,5.85 -8.1,6.15
3D body: height 0.2, standoff 0, extent -9.1,1.35 -8.1,1.65
3D body: height 0.2, standoff 0, extent -9.1,1.85 -8.1,2.15
3D body: height 0.2, standoff 0, extent -9.1,2.35 -8.1,2.65
3D body: height 0.2, standoff 0, extent -9.1,2.85 -8.1,3.15
3D body: height 0.2, standoff 0, extent -9.1,3.35 -8.1,3.65
3D body: height 0.2, standoff 0, extent -9.1,-1.15 -8.1,-0.85
3D body: height 0.2, standoff 0, extent -9.1,-0.65 -8.1,-0.35
3D body: height 0.2, standoff 0, extent -9.1,-0.15 -8.1,0.15
3D body: height 0.2, standoff 0, extent -9.1,0.35 -8.1,0.65
3D body: height 0.2, standoff 0, extent -9.1,0.85 -8.1,1.15
3D body: height 0.2, standoff 0, extent -9.1,-3.65 -8.1,-3.35
3D body: height 0.2, standoff 0, extent -9.1,-3.15 -8.1,-2.85
3D body: height 0.2, standoff 0, extent -9.1,-2.65 -8.1,-2.35
3D body: height 0.2, standoff 0, extent -9.1,-2.15 -8.1,-1.85
3D body: height 0.2, standoff 0, extent -9.1,-1.65 -8.1,-1.35
3D body: height 0.2, standoff 0, extent -9.1,-6.15 -8.1,-5.85
3D body: height 0.2, standoff 0, extent -9.1,-5.65 -8.1,-5.35
3D body: height 0.2, standoff 0, extent -9.1,-5.15 -8.1,-4.85
3D body: height 0.2, standoff 0, extent -9.1,-4.65 -8.1,-4.35
3D body: height 0.2, standoff 0, extent -9.1,-4.15 -8.1,-3.85
3D body: height 0.2, standoff 0, extent -4.15,-9.1 -3.85,-8.1
3D body: height 0.2, standoff 0, extent -4.65,-9.1 -4.35,-8.1
3D body: height 0.2, standoff 0, extent -5.15,-9.1 -4.85,-8.1
3D body: height 0.2, standoff 0, extent -5.65,-9.1 -5.35,-8.1
3D body: height 0.2, standoff 0, extent -6.15,-9.1 -5.85,-8.1
3D body: height 0.2, standoff 0, extent -1.65,-9.1 -1.35,-8.1
3D body: height 0.2, standoff 0, extent -2.15,-9.1 -1.85,-8.1
3D body: height 0.2, standoff 0, extent -2.65,-9.1 -2.35,-8.1
3D body: height 0.2, standoff 0, extent -3.15,-9.1 -2.85,-8.1
3D body: height 0.2, standoff 0, extent -3.65,-9.1 -3.35,-8.1
3D body: height 0.2, standoff 0, extent 0.85,-9.1 1.15,-8.1
3D body: height 0.2, standoff 0, extent 0.35,-9.1 0.65,-8.1
3D body: height 0.2, standoff 0, extent -0.15,-9.1 0.15,-8.1
3D body: height 0.2, standoff 0, extent -0.65,-9.1 -0.35,-8.1
3D body: height 0.2, standoff 0, extent -1.15,-9.1 -0.85,-8.1
3D body: height 0.2, standoff 0, extent 3.35,-9.1 3.65,-8.1
3D body: height 0.2, standoff 0, extent 2.85,-9.1 3.15,-8.1
3D body: height 0.2, standoff 0, extent 2.35,-9.1 2.65,-8.1
3D body: height 0.2, standoff 0, extent 1.85,-9.1 2.15,-8.1
3D body: height 0.2, standoff 0, extent 1.35,-9.1 1.65,-8.1
3D body: height 0.2, standoff 0, extent 5.85,-9.1 6.15,-8.1
3D body: height 0.2, standoff 0, extent 5.35,-9.1 5.65,-8.1
3D body: height 0.2, standoff 0, extent 4.85,-9.1 5.15,-8.1
3D body: height 0.2, standoff 0, extent 4.35,-9.1 4.65,-8.1
3D body: height 0.2, standoff 0, extent 3.85,-9.1 4.15,-8.1
3D body: height 0.2, standoff 0, extent 8.1,-4.15 9.1,-3.85
3D body: height 0.2, standoff 0, extent 8.1,-4.65 9.1,-4.35
3D body: height 0.2, standoff 0, extent 8.1,-5.15 9.1,-4.85
3D body: height 0.2, standoff 0, extent 8.1,-5.65 9.1,-5.35
3D body: height 0.2, standoff 0, extent 8.1,-6.15 9.1,-5.85
3D body: height 0.2, standoff 0, extent 8.1,-1.65 9.1,-1.35
3D body: height 0.2, standoff 0, extent 8.1,-2.15 9.1,-1.85
3D body: height 0.2, standoff 0, extent 8.1,-2.65 9.1,-2.35
3D body: height 0.2, standoff 0, extent 8.1,-3.15 9.1,-2.85
3D body: height 0.2, standoff 0, extent 8.1,-3.65 9.1,-3.35
3D body: height 0.2, standoff 0, extent 8.1,0.85 9.1,1.15
3D body: height 0.2, standoff 0, extent 8.1,0.35 9.1,0.65
3D body: height 0.2, standoff 0, extent 8.1,-0.15 9.1,0.15
3D body: height 0.2, standoff 0, extent 8.1,-0.65 9.1,-0.35
3D body: height 0.2, standoff 0, extent 8.1,-1.15 9.1,-0.85
3D body: height 0.2, standoff 0, extent 8.1,3.35 9.1,3.65
3D body: height 0.2, standoff 0, extent 8.1,2.85 9.1,3.15
3D body: height 0.2, standoff 0, extent 8.1,2.35 9.1,2.65
3D body: height 0.2, standoff 0, extent 8.1,1.85 9.1,2.15
3D body: height 0.2, standoff 0, extent 8.1,1.35 9.1,1.65
3D body: height 0.2, standoff 0, extent 8.1,5.85 9.1,6.15
3D body: height 0.2, standoff 0, extent 8.1,5.35 9.1,5.65
3D body: height 0.2, standoff 0, extent 8.1,4.85 9.1,5.15
3D body: height 0.2, standoff 0, extent 8.1,4.35 9.1,4.65
3D body: height 0.2, standoff 0, extent 8.1,3.85 9.1,4.15
3D body: height 0.2, standoff 0, extent 3.85,8.1 4.15,9.1
3D body: height 0.2, standoff 0, extent 4.35,8.1 4.65,9.1
3D body: height 0.2, standoff 0, extent 4.85,8.1 5.15,9.1
3D body: height 0.2, standoff 0, extent 5.35,8.1 5.65,9.1
3D body: height 0.2, standoff 0, extent 5.85,8.1 6.15,9.1
3D body: height 0.2, standoff 0, extent 1.35,8.1 1.65,9.1
3D body: height 0.2, standoff 0, extent 1.85,8.1 2.15,9.1
3D body: height 0.2, standoff 0, extent 2.35,8.1 2.65,9.1
3D body: height 0.2, standoff 0, extent 2.85,8.1 3.15,9.1
3D body: height 0.2, standoff 0, extent 3.35,8.1 3.65,9.1
3D body: height 0.2, standoff 0, extent -1.15,8.1 -0.85,9.1
3D body: height 0.2, standoff 0, extent -0.65,8.1 -0.35,9.1
3D body: height 0.2, standoff 0, extent -0.15,8.1 0.15,9.1
3D body: height 0.2, standoff 0, extent 0.35,8.1 0.65,9.1
3D body: height 0.2, standoff 0, extent 0.85,8.1 1.15,9.1
3D body: height 0.2, standoff 0, extent -3.65,8.1 -3.35,9.1
3D body: height 0.2, standoff 0, extent -3.15,8.1 -2.85,9.1
3D body: height 0.2, standoff 0, extent -2.65,8.1 -2.35,9.1
3D body: height 0.2, standoff 0, extent -2.15,8.1 -1.85,9.1
3D body: height 0.2, standoff 0, extent -1.65,8.1 -1.35,9.1
3D body: height 0.2, standoff 0, extent -4.15,8.1 -3.85,9.1
3D body: height 0.2, standoff 0, extent -4.65,8.1 -4.35,9.1
3D body: height 0.2, standoff 0, extent -5.15,8.1 -4.85,9.1
3D body: height 0.2, standoff 0, extent -5.65,8.1 -5.35,9.1
3D body: height 13.2, standoff 12.2, extent -10.2,10.2 -7.9,12.5
3D body: height 13.2, standoff 12.2, extent -10.2,7.9 -7.9,10.2
3D body: height 13.2, standoff 12.2, extent -12.5,7.9 -10.2,10.2
3D body: height 13.2, standoff 12.2, extent -12.5,10.2 -10.2,12.5
3D body: height 12.2, standoff 11.2, extent -12.5,7.9 -7.9,12.5
3D body: height 11.2, standoff 11, extent -12.7,7.703 -7.7,12.697
3D body "LQFP100_05.STEP": height 7.1, standoff 5.5, extent -8,-8 8,8
3D body: height 0.2, standoff 0, extent -6.15,8.1 -5.85,9.1
3D body: height 11.2, standoff 11, extent 7.7,7.703 12.7,12.697
3D body: height 12.2, standoff 11.2, extent 7.9,7.9 12.5,12.5
3D body: height 13.2, standoff 12.2, extent 7.9,10.2 10.2,12.5
3D body: height 13.2, standoff 12.2, extent 7.9,7.9 10.2,10.2
3D body: height 13.2, standoff 12.2, extent 10.2,7.9 12.5,10.2
3D body: height 13.2, standoff 12.2, extent 10.2,10.2 12.5,12.5
3D body: height 11.2, standoff 11, extent 7.7,-12.697 12.7,-7.703
3D body: height 12.2, standoff 11.2, extent 7.9,-12.5 12.5,-7.9
3D body: height 13.2, standoff 12.2, extent 7.9,-10.2 10.2,-7.9
3D body: height 13.2, standoff 12.2, extent 7.9,-12.5 10.2,-10.2
3D body: height 13.2, standoff 12.2, extent 10.2,-12.5 12.5,-10.2
3D body: height 13.2, standoff 12.2, extent 10.2,-10.2 12.5,-7.9
3D body: height 11.2, standoff 11, extent -12.7,-12.697 -7.7,-7.703
3D body: height 12.2, standoff 11.2, extent -12.5,-12.5 -7.9,-7.9
3D body: height 13.2, standoff 12.2, extent -12.5,-10.2 -10.2,-7.9
3D body: height 13.2, standoff 12.2, extent -12.5,-12.5 -10.2,-10.2
3D body: height 13.2, standoff 12.2, extent -10.2,-12.5 -7.9,-10.2
3D body: height 13.2, standoff 12.2, extent -10.2,-10.2 -7.9,-7.9
3D body: height 3.5, standoff 0, extent -9.297,6.825 -6.823,9.3
3D body: height 3.5, standoff 0, extent 6.825,6.823 9.3,9.297
3D body: height 3.5, standoff 0, extent 6.823,-9.3 9.297,-6.825
3D body: height 3.5, standoff 0, extent -9.3,-9.297 -6.825,-6.823
3D body: height 5.5, standoff 0, extent -8.1,-8.1 8.1,8.1
3D body: height 3.5, standoff 0.2, extent -6.15,8.1 -5.85,8.35
3D body: height 3.5, standoff 0.2, extent -5.65,8.1 -5.35,8.35
3D body: height 3.5, standoff 0.2, extent -5.15,8.1 -4.85,8.35
3D body: height 3.5, standoff 0.2, extent -4.65,8.1 -4.35,8.35
3D body: height 3.5, standoff 0.2, extent -4.15,8.1 -3.85,8.35
3D body: height 3.5, standoff 0.2, extent -1.65,8.1 -1.35,8.35
3D body: height 3.5, standoff 0.2, extent -2.15,8.1 -1.85,8.35
3D body: height 3.5, standoff 0.2, extent -2.65,8.1 -2.35,8.35
3D body: height 3.5, standoff 0.2, extent -3.15,8.1 -2.85,8.35
3D body: height 3.5, standoff 0.2, extent -3.65,8.1 -3.35,8.35
3D body: height 3.5, standoff 0.2, extent 0.85,8.1 1.15,8.35
3D body: height 3.5, standoff 0.2, extent 0.35,8.1 0.65,8.35
3D body: height 3.5, standoff 0.2, extent -0.15,8.1 0.15,8.35
3D body: height 3.5, standoff 0.2, extent -0.65,8.1 -0.35,8.35
3D body: height 3.5, standoff 0.2, extent -1.15,8.1 -0.85,8.35
3D body: height 3.5, standoff 0.2, extent 3.35,8.1 3.65,8.35
3D body: height 3.5, standoff 0.2, extent 2.85,8.1 3.15,8.35
3D body: height 3.5, standoff 0.2, extent 2.35,8.1 2.65,8.35
3D body: height 3.5, standoff 0.2, extent 1.85,8.1 2.15,8.35
3D body: height 3.5, standoff 0.2, extent 1.35,8.1 1.65,8.35
3D body: height 3.5, standoff 0.2, extent 5.85,8.1 6.15,8.35
3D body: height 3.5, standoff 0.2, extent 5.35,8.1 5.65,8.35
3D body: height 3.5, standoff 0.2, extent 4.85,8.1 5.15,8.35
3D body: height 3.5, standoff 0.2, extent 4.35,8.1 4.65,8.35
3D body: height 3.5, standoff 0.2, extent 3.85,8.1 4.15,8.35
3D body: height 3.5, standoff 0.2, extent 8.1,3.85 8.35,4.15
3D body: height 3.5, standoff 0.2, extent 8.1,4.35 8.35,4.65
3D body: height 3.5, standoff 0.2, extent 8.1,4.85 8.35,5.15
3D body: height 3.5, standoff 0.2, extent 8.1,5.35 8.35,5.65
3D body: height 3.5, standoff 0.2, extent 8.1,5.85 8.35,6.15
3D body: height 3.5, standoff 0.2, extent 8.1,1.35 8.35,1.65
3D body: height 3.5, standoff 0.2, extent 8.1,1.85 8.35,2.15
3D body: height 3.5, standoff 0.2, extent 8.1,2.35 8.35,2.65
3D body: height 3.5, standoff 0.2, extent 8.1,2.85 8.35,3.15
3D body: height 3.5, standoff 0.2, extent 8.1,3.35 8.35,3.65
3D body: height 3.5, standoff 0.2, extent 8.1,-1.15 8.35,-0.85
3D body: height 3.5, standoff 0.2, extent 8.1,-0.65 8.35,-0.35
3D body: height 3.5, standoff 0.2, extent 8.1,-0.15 8.35,0.15
3D body: height 3.5, standoff 0.2, extent 8.1,0.35 8.35,0.65
3D body: height 3.5, standoff 0.2, extent 8.1,0.85 8.35,1.15
3D body: height 3.5, standoff 0.2, extent 8.1,-3.65 8.35,-3.35
3D body: height 3.5, standoff 0.2, extent 8.1,-3.15 8.35,-2.85
3D body: height 3.5, standoff 0.2, extent 8.1,-2.65 8.35,-2.35
3D body: height 3.5, standoff 0.2, extent 8.1,-2.15 8.35,-1.85
3D body: height 3.5, standoff 0.2, extent 8.1,-1.65 8.35,-1.35
3D body: height 3.5, standoff 0.2, extent 8.1,-6.15 8.35,-5.85
3D body: height 3.5, standoff 0.2, extent 8.1,-5.65 8.35,-5.35
3D body: height 3.5, standoff 0.2, extent 8.1,-5.15 8.35,-4.85
3D body: height 3.5, standoff 0.2, extent 8.1,-4.65 8.35,-4.35
3D body: height 3.5, standoff 0.2, extent 8.1,-4.15 8.35,-3.85
3D body: height 3.5, standoff 0.2, extent 3.85,-8.35 4.15,-8.1
3D body: height 3.5, standoff 0.2, extent 4.35,-8.35 4.65,-8.1
3D body: height 3.5, standoff 0.2, extent 4.85,-8.35 5.15,-8.1
3D body: height 3.5, standoff 0.2, extent 5.35,-8.35 5.65,-8.1
3D body: height 3.5, standoff 0.2, extent 5.85,-8.35 6.15,-8.1
3D body: height 3.5, standoff 0.2, extent 1.35,-8.35 1.65,-8.1
3D body: height 3.5, standoff 0.2, extent 1.85,-8.35 2.15,-8.1
3D body: height 3.5, standoff 0.2, extent 2.35,-8.35 2.65,-8.1
3D body: height 3.5, standoff 0.2, extent 2.85,-8.35 3.15,-8.1
3D body: height 3.5, standoff 0.2, extent 3.35,-8.35 3.65,-8.1
3D body: height 3.5, standoff 0.2, extent -1.15,-8.35 -0.85,-8.1
3D body: height 3.5, standoff 0.2, extent -0.65,-8.35 -0.35,-8.1
3D body: height 3.5, standoff 0.2, extent -0.15,-8.35 0.15,-8.1
3D body: height 3.5, standoff 0.2, extent 0.35,-8.35 0.65,-8.1
3D body: height 3.5, standoff 0.2, extent 0.85,-8.35 1.15,-8.1
3D body: height 3.5, standoff 0.2, extent -3.65,-8.35 -3.35,-8.1
3D body: height 3.5, standoff 0.2, extent -3.15,-8.35 -2.85,-8.1
3D body: height 3.5, standoff 0.2, extent -2.65,-8.35 -2.35,-8.1
3D body: height 3.5, standoff 0.2, extent -2.15,-8.35 -1.85,-8.1
3D body: height 3.5, standoff 0.2, extent -1.65,-8.35 -1.35,-8.1
3D body: height 3.5, standoff 0.2, extent -6.15,-8.35 -5.85,-8.1
3D body: height 3.5, standoff 0.2, extent -5.65,-8.35 -5.35,-8.1
3D body: height 3.5, standoff 0.2, extent -5.15,-8.35 -4.85,-8.1
3D body: height 3.5, standoff 0.2, extent -4.65,-8.35 -4.35,-8.1
3D body: height 3.5, standoff 0.2, extent -4.15,-8.35 -3.85,-8.1
3D body: height 3.5, standoff 0.2, extent -8.35,-4.15 -8.1,-3.85
3D body: height 3.5, standoff 0.2, extent -8.35,-4.65 -8.1,-4.35
3D body: height 3.5, standoff 0.2, extent -8.35,-5.15 -8.1,-4.85
3D body: height 3.5, standoff 0.2, extent -8.35,-5.65 -8.1,-5.35
3D body: height 3.5, standoff 0.2, extent -8.35,-6.15 -8.1,-5.85
3D body: height 3.5, standoff 0.2, extent -8.35,-1.65 -8.1,-1.35
3D body: height 3.5, standoff 0.2, extent -8.35,-2.15 -8.1,-1.85
3D body: height 3.5, standoff 0.2, extent -8.35,-2.65 -8.1,-2.35
3D body: height 3.5, standoff 0.2, extent -8.35,-3.15 -8.1,-2.85
3D body: height 3.5, standoff 0.2, extent -8.35,-3.65 -8.1,-3.35
3D body: height 3.5, standoff 0.2, extent -8.35,0.85 -8.1,1.15
3D body: height 3.5, standoff 0.2, extent -8.35,0.35 -8.1,0.65
3D body: height 3.5, standoff 0.2, extent -8.35,-0.15 -8.1,0.15
3D body: height 3.5, standoff 0.2, extent -8.35,-0.65 -8.1,-0.35
3D body: height 3.5, standoff 0.2, extent -8.35,-1.15 -8.1,-0.85
3D body: height 3.5, standoff 0.2, extent -8.35,3.35 -8.1,3.65
3D body: height 3.5, standoff 0.2, extent -8.35,2.85 -8.1,3.15
3D body: height 3.5, standoff 0.2, extent -8.35,2.35 -8.1,2.65
3D body: height 3.5, standoff 0.2, extent -8.35,1.85 -8.1,2.15
3D body: height 3.5, standoff 0.2, extent -8.35,1.35 -8.1,1.65
3D body: height 3.5, standoff 0.2, extent -8.35,5.85 -8.1,6.15
3D body: height 3.5, standoff 0.2, extent -8.35,5.35 -8.1,5.65
3D body: height 3.5, standoff 0.2, extent -8.35,4.85 -8.1,5.15
3D body: height 3.5, standoff 0.2, extent -8.35,4.35 -8.1,4.65
3D body: height 3.5, standoff 0.2, extent -8.35,3.85 -8.1,4.15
